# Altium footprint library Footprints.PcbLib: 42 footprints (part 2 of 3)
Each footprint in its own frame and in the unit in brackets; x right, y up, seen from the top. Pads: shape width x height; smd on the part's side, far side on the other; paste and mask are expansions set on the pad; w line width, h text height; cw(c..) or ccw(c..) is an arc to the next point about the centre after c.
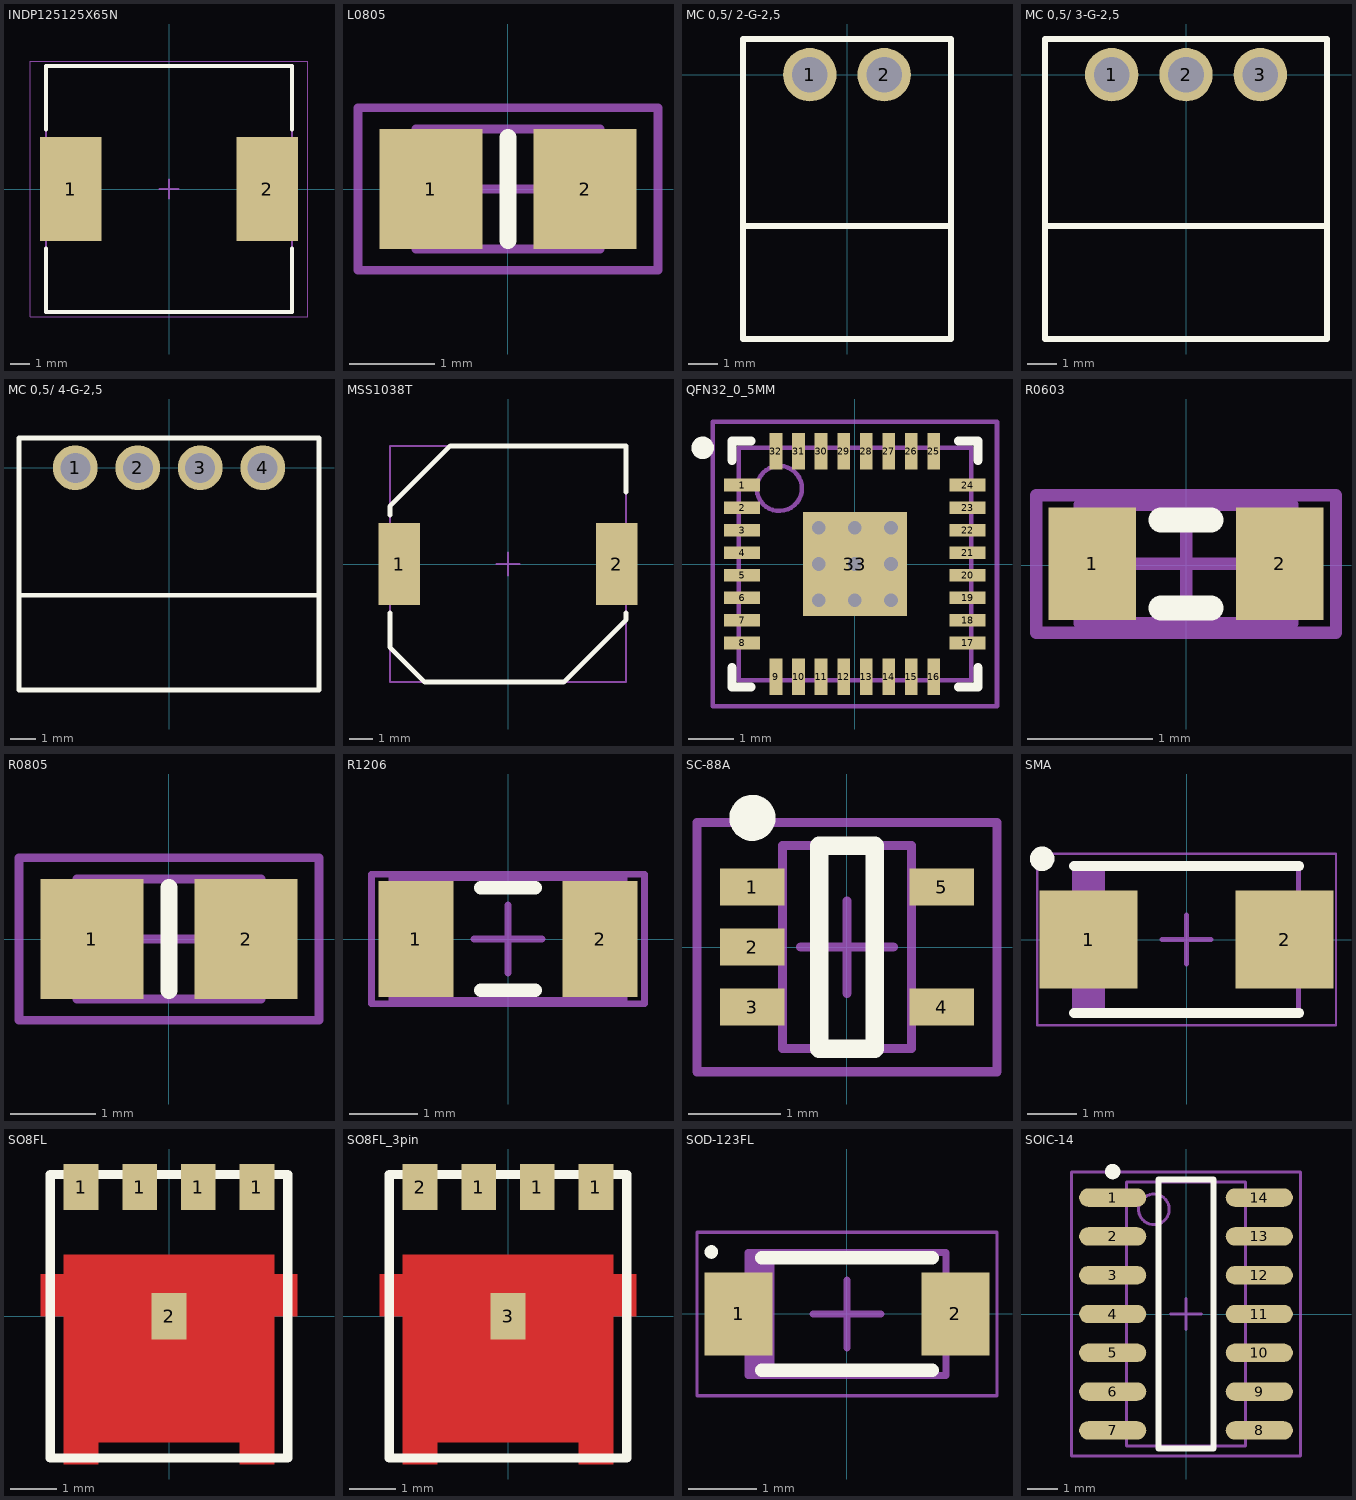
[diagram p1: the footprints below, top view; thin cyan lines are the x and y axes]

## INDP125125X65N [mm] "Precision Wire Wound Inductor, 2-Leads, Body 12.50x12.50mm, IPC Medium Density"
height 6.5
pads (2):
  rect 3.2x5.4 smd: 1(-5.1,0) 2(5.1,0)
Top Overlay:
  lines w0.2: -6.4,-3.1 -6.4,-6.4 6.4,-6.4 6.4,-3.1 ; -6.4,3.1 -6.4,6.4 6.4,6.4 6.4,3.1
Mechanical 13:
  lines w0.1: -6.4,-6.4 6.4,-6.4 6.4,6.4 -6.4,6.4 -6.4,-6.4
Mechanical 15:
  lines w0.05: -7.225,-6.65 7.225,-6.65 7.225,6.65 -7.225,6.65 -7.225,-6.65
  lines w0.1: -0.5,0 0.5,0 ; 0,-0.5 0,0.5
3D body: height 4.6, standoff -0.2, extent -6.1,-6.1 6.1,6.1

## L0805 [mm] "Chip Resistor, Body 2.0x1.2mm, IPC Medium Density"
height 0.7
pads (2):
  rect 1.2x1.4 smd: 1(-0.9,0) 2(0.9,0)
Top Overlay:
  lines w0.2: 0,-0.6 0,0.6
Mechanical 13:
  lines w0.1: -1.075,-0.7 1.075,-0.7 1.075,0.7 -1.075,0.7 -1.075,-0.7
Mechanical 15:
  lines w0.1: -0.5,0 0.5,0 ; 0,-0.5 0,0.5 ; -1.75,-0.95 1.75,-0.95 1.75,0.95 -1.75,0.95 -1.75,-0.95
3D body: height 1.3, standoff 0, extent -1,-0.6 1,0.6

## MC 0,5/ 2-G-2,5 [mm] "Phoenix Contacts 2 pin header - pitch 2.5mm"
height 8.1
pads (2):
  round 1.8 hole 1.2: 1(-1.25,0) 2(1.25,0)
Top Overlay:
  lines w0.2: -3.5,-5.1 3.5,-5.1 ; -3.5,-8.9 -3.5,1.2 3.5,1.2 3.5,-8.9 -3.5,-8.9
Mechanical 13:
  lines w0.1: -3.5,-8.9 3.5,-8.9 3.5,1.2 -3.5,1.2 -3.5,-8.9
3D body: height 8.1, standoff -3.5, extent -3.45,-8.9 3.45,1.2

## MC 0,5/ 3-G-2,5 [mm] "Phoenix Contacts 3 pin header - pitch 2.5mm"
height 8.1
pads (3):
  round 1.8 hole 1.2: 1(-2.5,0) 2(0,0) 3(2.5,0)
Top Overlay:
  lines w0.2: -4.75,-5.1 4.7,-5.1 ; 4.7,-8.9 -4.75,-8.9 -4.75,1.2 4.75,1.2 4.75,-8.9
Mechanical 13:
  lines w0.1: -4.75,-8.9 4.7,-8.9 4.7,1.2 -4.75,1.2 -4.75,-8.9
3D body: height 8.1, standoff -3.5, extent -4.7,-8.9 4.7,1.2

## MC 0,5/ 4-G-2,5 [mm] "Phoenix Contacts 4 pin header - pitch 2.5mm"
height 8.1
pads (4):
  round 1.8 hole 1.2: 1(-3.75,0) 2(-1.25,0) 3(1.25,0) 4(3.75,0)
Top Overlay:
  lines w0.2: -6,-5.1 6,-5.1 ; -6,-8.9 6,-8.9 6,1.2 -6,1.2 -6,-8.9
Mechanical 13:
  lines w0.1: -6,-8.9 -6,1.2 6,1.2 6,-8.9 -6,-8.9
3D body: height 8.1, standoff -3.5, extent -5.95,-8.9 5.95,1.2

## MSS1038T [mm] "Precision Wire Wound Inductor, 2-Leads, Coilcraft MSS2038T 10x10mm"
height 4
pads (2):
  rect 1.78x3.56 smd: 1(-4.7,0) 2(4.7,0)
Top Overlay:
  lines w0.2: -5.1,-2.1 -5.1,-3.6 -3.6,-5.1 2.4,-5.1 5.1,-2.4 5.1,-2.1 ; -5.1,2.1 -5.1,2.5 -2.5,5.1 5.1,5.1 5.1,3.1
Mechanical 13:
  lines w0.1: -5.1,-5.1 5.1,-5.1 ; -5.1,-5.1 -5.1,5.1 5.1,5.1 5.1,-5.1 ; -5.1,-5.1 5.1,-5.1
Mechanical 15:
  lines w0.1: -0.5,0 0.5,0 ; 0,-0.5 0,0.5
3D body: height 3.9, standoff -0.1, extent -5.15,-5.1 5.15,5.1

## QFN32_0_5MM [mm] "QFN, 32-Leads, Body 5x5mm, Pitch 0.5mm, IPC Medium Density"
height 1
pads (33):
  rect 0.8x0.28 smd: 1(-2.5,1.75) 2(-2.5,1.25) 3(-2.5,0.75) 4(-2.5,0.25) 5(-2.5,-0.25) 6(-2.5,-0.75) 7(-2.5,-1.25) 8(-2.5,-1.75) 17(2.5,-1.75) 18(2.5,-1.25) 19(2.5,-0.75) 20(2.5,-0.25) 21(2.5,0.25) 22(2.5,0.75) 23(2.5,1.25) 24(2.5,1.75)
  rect 0.28x0.8 smd: 9(-1.75,-2.5) 10(-1.25,-2.5) 11(-0.75,-2.5) 12(-0.25,-2.5) 13(0.25,-2.5) 14(0.75,-2.5) 15(1.25,-2.5) 16(1.75,-2.5) 25(1.75,2.5) 26(1.25,2.5) 27(0.75,2.5) 28(0.25,2.5) 29(-0.25,2.5) 30(-0.75,2.5) 31(-1.25,2.5) 32(-1.75,2.5)
  rect 2.3x2.3 smd: 33(0,0)
via 0.8,0 diameter 0.7 hole 0.3
via 0.8,-0.8 diameter 0.7 hole 0.3
via -0.8,-0.8 diameter 0.7 hole 0.3
via -0.8,0 diameter 0.7 hole 0.3
via -0.8,0.8 diameter 0.7 hole 0.3
via 0.8,0.8 diameter 0.7 hole 0.3
via 0,0.8 diameter 0.7 hole 0.3
via 0,-0.8 diameter 0.7 hole 0.3
via 0,0 diameter 0.7 hole 0.3
Top Overlay:
  circle w0.25: c-3.375,2.575 r0.125
  lines w0.2: -2.725,-2.3 -2.725,-2.725 -2.3,-2.725 ; -2.725,2.3 -2.725,2.725 -2.3,2.725 ; 2.3,-2.725 2.725,-2.725 2.725,-2.3 ; 2.3,2.725 2.725,2.725 2.725,2.3
Mechanical 13:
  circle w0.1: c-1.675,1.675 r0.5
  lines w0.1: -2.575,-2.575 -2.575,2.575 2.575,2.575 2.575,-2.575 -2.575,-2.575
Mechanical 15:
  lines w0.1: -0.5,0 0.5,0 ; 0,-0.5 0,0.5 ; -3.15,-3.15 -3.15,3.15 3.15,3.15 3.15,-3.15 -3.15,-3.15
3D body: height 0.8, standoff -0.05, extent -2.5,-2.5 2.5,2.5

## R0603 [mm]
height 0.9
pads (2):
  rect 0.7x0.9 smd: 1(-0.751,0.008) 2(0.749,0.008)
Top Overlay:
  lines w0.2: -0.201,-0.342 0.199,-0.342 ; -0.201,0.358 0.199,0.358
Mechanical 13:
  lines w0.1: -0.851,-0.467 0.849,-0.467 0.849,0.483 -0.851,0.483 -0.851,-0.467
Mechanical 15:
  lines w0.1: -0.476,0.008 0.474,0.008 ; -0.001,-0.467 -0.001,0.483 ; -1.201,-0.542 1.199,-0.542 1.199,0.558 -1.201,0.558 -1.201,-0.542
3D body: height 0.5, standoff 0, extent -0.801,-0.392 0.799,0.408

## R0805 [mm] "Chip Resistor, Body 2.0x1.2mm, IPC Medium Density"
height 0.7
pads (2):
  rect 1.2x1.4 smd: 1(-0.9,0) 2(0.9,0)
Top Overlay:
  lines w0.2: 0,-0.6 0,0.6
Mechanical 13:
  lines w0.1: -1.075,-0.7 -1.075,0.7 1.075,0.7 1.075,-0.7 -1.075,-0.7
Mechanical 15:
  lines w0.1: -0.5,0 0.5,0 ; 0,-0.5 0,0.5 ; -1.75,-0.95 -1.75,0.95 1.75,0.95 1.75,-0.95 -1.75,-0.95
3D body: height 0.5, standoff 0, extent -1,-0.6 1,0.6

## R1206 [mm] "Chip Resistor, Body 3.2x1.6mm, IPC High Density"
height 1.3
pads (2):
  rect 1.1x1.7 smd: 1(-1.35,0) 2(1.35,0)
Top Overlay:
  lines w0.2: -0.4,-0.75 0.4,-0.75 ; -0.4,0.75 0.4,0.75
Mechanical 13:
  lines w0.1: -1.7,-0.9 1.7,-0.9 1.7,0.9 -1.7,0.9 -1.7,-0.9
Mechanical 15:
  lines w0.1: -0.5,0 0.5,0 ; 0,-0.5 0,0.5 ; -2,-0.95 2,-0.95 2,0.95 -2,0.95 -2,-0.95
3D body: height 0.6, standoff 0, extent -1.6,-0.8 1.6,0.8

## SC-88A [mm] "SOT353, 5-Leads, Body 2x1.3mm, Pitch 0.65mm, Lead Span 2.1mm, IPC Medium Density"
height 1.1
pads (5):
  rect 0.7x0.4 smd mask+0: 1(-1.025,0.65) 2(-1.025,0) 3(-1.025,-0.65)
  rect 0.7x0.4 smd: 4(1.025,-0.65) 5(1.025,0.65)
Top Overlay:
  circle w0.25: c-1.025,1.4 r0.125
  lines w0.2: -0.3,-1.1 -0.3,1.1 0.3,1.1 0.3,-1.1 -0.3,-1.1
Top Solder:
  rectangle: -1.475,-0.95 -0.575,0.95
Mechanical 13:
  lines w0.1: -0.7,-1.1 0.7,-1.1 0.7,1.1 -0.7,1.1 -0.7,-1.1
Mechanical 15:
  lines w0.1: -0.5,0 0.5,0 ; 0,-0.5 0,0.5 ; -1.625,-1.35 1.625,-1.35 1.625,1.35 -1.625,1.35 -1.625,-1.35
3D body: height 1, standoff 0, extent -1.15,-1.05 1.15,1.05

## SMA [mm] "Molded Diode, 2-Leads, Body 4.31x2.60mm, IPC Medium Density"
height 2.2
pads (2):
  rect 2x2 smd: 1(-2,0) 2(2,0)
Top Overlay:
  circle w0.25: c-2.95,1.65 r0.125
  lines w0.2: -2.3,-1.5 2.3,-1.5 ; -2.3,1.5 2.3,1.5
Mechanical 13:
  rectangle: -2.285,-1.46 -1.67,1.46
  lines w0.1: -2.285,-1.46 2.285,-1.46 2.285,1.46 -2.285,1.46 -2.285,-1.46
Mechanical 15:
  lines w0.05: -3.05,-1.75 3.05,-1.75 3.05,1.75 -3.05,1.75 -3.05,-1.75
  lines w0.1: -0.5,0 0.5,0 ; 0,-0.5 0,0.5
3D body: height 2.6, standoff 0.03, extent -2.75,-1.4 2.75,1.4

## SO8FL [mm]
height 1
pads (5):
  rect 0.75x1 smd: 1(-1.905,2.795) 1(-0.635,2.795) 1(0.635,2.795) 1(1.905,2.795) 2(0,0)
Top Layer:
  region: -2.28,1.33 -2.28,0.905 -2.775,0.905 -2.775,0 -2.28,0 -2.28,-3.2 -1.53,-3.2 -1.53,-2.725 1.53,-2.725 1.53,-3.2 2.28,-3.2 2.28,0 2.775,0 2.775,0.905 2.28,0.905 2.28,1.33
Top Overlay:
  lines w0.2: -2.57,-3.07 2.57,-3.07 2.57,3.07 -2.57,3.07 -2.57,-3.07
3D body: height 1.13, standoff 0, extent -2.575,-3.05 2.575,3.1

## SO8FL_3pin [mm]
height 1
pads (5):
  rect 0.75x1 smd: 1(-0.635,2.795) 1(0.635,2.795) 1(1.905,2.795) 2(-1.905,2.795) 3(0,0)
Top Layer:
  region: -2.28,1.33 -2.28,0.905 -2.775,0.905 -2.775,0 -2.28,0 -2.28,-3.2 -1.53,-3.2 -1.53,-2.725 1.53,-2.725 1.53,-3.2 2.28,-3.2 2.28,0 2.775,0 2.775,0.905 2.28,0.905 2.28,1.33
Top Overlay:
  lines w0.2: -2.57,-3.07 -2.57,3.07 2.57,3.07 2.57,-3.07 -2.57,-3.07
3D body: height 1, standoff 0, extent -2.57,-3.07 2.57,3.07

## SOD-123FL [mm] "Molded Diode, 2-Leads, Body 2.70x1.65mm, IPC Medium Density"
height 1
pads (2):
  rect 1x1.22 smd: 1(-1.59,0) 2(1.59,0)
Top Overlay:
  circle w0.1: c-1.99,0.91 r0.05
  lines w0.2: -1.25,-0.825 1.25,-0.825 ; -1.25,0.825 1.25,0.825
Mechanical 13:
  rectangle: -1.45,-0.9 -1.06,0.9
  lines w0.1: -1.45,-0.9 1.45,-0.9 1.45,0.9 -1.45,0.9 -1.45,-0.9
Mechanical 15:
  lines w0.05: -2.2,-1.2 2.2,-1.2 2.2,1.2 -2.2,1.2 -2.2,-1.2
  lines w0.1: -0.5,0 0.5,0 ; 0,-0.5 0,0.5
3D body: height 1, standoff 0, extent -1.45,-0.9 1.45,0.9

## SOIC-14 [mm] "14-Pin Small Outline Integrated Circuit 1.27 mm Pitch, IPC Medium Density"
height 1.75
pads (14):
  oval 2.2x0.6 smd: 1(-2.4,3.81) 2(-2.4,2.54) 3(-2.4,1.27) 4(-2.4,0) 5(-2.4,-1.27) 6(-2.4,-2.54) 7(-2.4,-3.81) 8(2.4,-3.81) 9(2.4,-2.54) 10(2.4,-1.27) 11(2.4,0) 12(2.4,1.27) 13(2.4,2.54) 14(2.4,3.81)
Top Overlay:
  circle w0.25: c-2.4,4.66 r0.125
  lines w0.2: -0.9,-4.4 -0.9,4.4 0.9,4.4 0.9,-4.4 -0.9,-4.4
Mechanical 13:
  circle w0.1: c-1.05,3.425 r0.5
  lines w0.1: -1.95,-4.325 -1.95,4.325 1.95,4.325 1.95,-4.325 -1.95,-4.325
Mechanical 15:
  lines w0.1: -0.5,0 0.5,0 ; 0,-0.5 0,0.5 ; -3.75,-4.65 -3.75,4.65 3.75,4.65 3.75,-4.65 -3.75,-4.65
3D body: height 1.75, standoff 0, extent -1.95,-4.325 1.95,4.325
